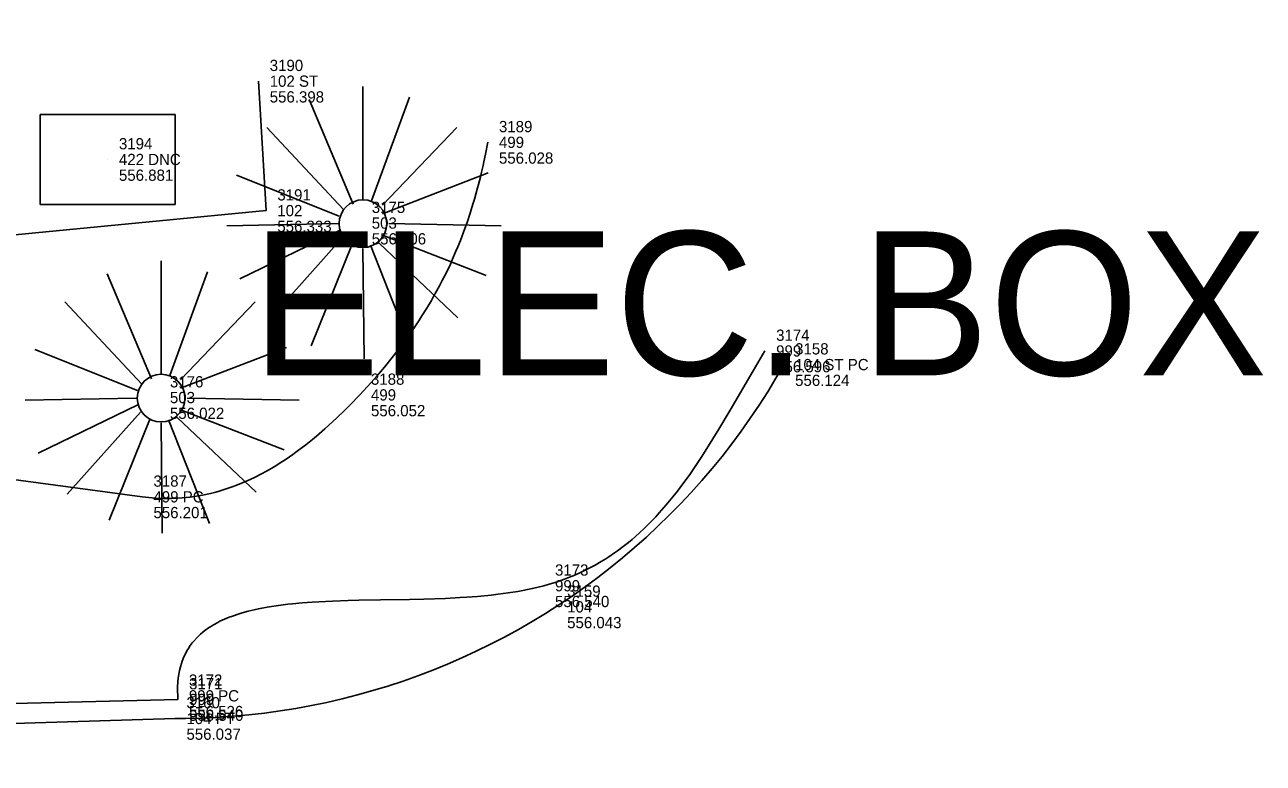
# Model space of a CAD drawing. Extents: x 5447 to 709667, y 4528 to 375505.
# Drawn here: x 708330.63 to 708358.18, y 374261.75 to 374278.17 of the extents above; entities that cross this region are included whole.
import ezdxf

# ---------------------------------------------------------------- set-up
doc = ezdxf.new("R2010")
doc.units = 0
for name, color, linetype in [('SV_BKLN_BKLN', 7, 'Continuous'), ('SV_NODES_ACTIVE_POINT', 7, 'Continuous'), ('SV_NODES_DESCRIPTION', 7, 'Continuous'), ('SV_NODES_ELEVATION', 7, 'Continuous'), ('SV_NODES_PT_NUMBER', 7, 'Continuous'), ('SV_ROAD_BCURB', 7, 'Continuous'), ('SV_ROAD_CONCRD', 7, 'Continuous'), ('SV_TREE_TREEVEG', 7, 'Continuous'), ('SV_UTAG_MISC_ELEC', 7, 'Continuous'), ('SV_UTAG_UTAG_TX', 7, 'Continuous')]:
    doc.layers.add(name, color=color, linetype=linetype)

msp = doc.modelspace()

# ---------------------------------------------------------------- linework, layer by layer
at = {"layer": 'SV_BKLN_BKLN'}
msp.add_lwpolyline([(708301.823, 374262.381), (708334.036, 374263.169), (708334.032, 374263.25), (708334.029, 374263.362), (708334.029, 374263.434), (708334.037, 374263.574), (708334.044, 374263.641), (708334.05, 374263.685), (708334.064, 374263.771), (708334.072, 374263.812), (708334.092, 374263.893), (708334.115, 374263.971), (708334.132, 374264.022), (708334.171, 374264.119), (708334.195, 374264.172), (708334.213, 374264.206), (708334.25, 374264.272), (708334.27, 374264.305), (708334.311, 374264.367), (708334.356, 374264.427), (708334.388, 374264.466), (708334.455, 374264.54), (708334.536, 374264.618), (708334.594, 374264.667), (708334.634, 374264.699), (708334.718, 374264.759), (708334.784, 374264.802), (708334.83, 374264.829), (708334.924, 374264.881), (708334.972, 374264.906), (708335.073, 374264.953), (708335.177, 374264.996), (708335.249, 374265.023), (708335.398, 374265.074), (708335.463, 374265.093), (708335.596, 374265.13), (708335.734, 374265.163), (708335.828, 374265.184), (708336.021, 374265.22), (708336.17, 374265.244), (708336.272, 374265.259), (708336.479, 374265.285), (708336.585, 374265.296), (708336.801, 374265.316), (708337.022, 374265.332), (708337.171, 374265.341), (708337.475, 374265.356), (708337.825, 374265.367), (708338.061, 374265.373), (708338.54, 374265.382), (708339.186, 374265.393), (708339.509, 374265.401), (708339.991, 374265.417), (708340.309, 374265.434), (708340.466, 374265.443), (708340.7, 374265.461), (708341.008, 374265.49), (708341.159, 374265.508), (708341.382, 374265.538), (708341.601, 374265.572), (708341.708, 374265.592), (708341.919, 374265.635), (708342.023, 374265.659), (708342.175, 374265.697), (708342.27, 374265.723), (708342.454, 374265.78), (708342.634, 374265.843), (708342.75, 374265.888), (708342.827, 374265.919), (708342.977, 374265.985), (708343.14, 374266.064), (708343.247, 374266.119), (708343.317, 374266.157), (708343.454, 374266.236), (708343.555, 374266.298), (708343.621, 374266.341), (708343.75, 374266.428), (708343.814, 374266.473), (708343.938, 374266.566), (708344.06, 374266.662), (708344.139, 374266.728), (708344.294, 374266.864), (708344.421, 374266.983), (708344.504, 374267.064), (708344.666, 374267.231), (708344.745, 374267.317), (708344.899, 374267.493), (708345.049, 374267.675), (708345.146, 374267.799), (708345.21, 374267.883), (708345.336, 374268.054), (708345.406, 374268.151), (708345.543, 374268.349), (708345.677, 374268.551), (708345.765, 374268.687), (708345.939, 374268.964), (708346.068, 374269.175), (708346.322, 374269.604), (708346.832, 374270.478), (708347.093, 374270.917)], dxfattribs=at)
at = {"layer": 'SV_NODES_ACTIVE_POINT'}
for p, q in [((708335.829, 374276.915), (708335.829, 374276.915)), ((708340.928, 374275.555), (708340.928, 374275.555)), ((708335.998, 374274.037), (708335.998, 374274.037)), ((708347.093, 374270.917), (708347.093, 374270.917)), ((708347.516, 374270.614), (708347.516, 374270.614)), ((708338.081, 374269.94), (708338.081, 374269.94)), ((708333.243, 374267.674), (708333.243, 374267.674)), ((708342.175, 374265.697), (708342.175, 374265.697)), ((708342.445, 374265.228), (708342.445, 374265.228)), ((708334.032, 374263.25), (708334.032, 374263.25)), ((708334.036, 374263.169), (708334.036, 374263.169)), ((708333.977, 374262.747), (708333.977, 374262.747))]:
    msp.add_line(p, q, dxfattribs=at)
at = {"layer": 'SV_ROAD_BCURB'}
msp.add_lwpolyline([(708347.516, 374270.614), (708347.34, 374270.31), (708347.156, 374270.009), (708346.966, 374269.713), (708346.769, 374269.422), (708346.566, 374269.134), (708346.356, 374268.852), (708346.14, 374268.574), (708345.917, 374268.302), (708345.689, 374268.034), (708345.454, 374267.772), (708345.214, 374267.515), (708344.967, 374267.264), (708344.715, 374267.018), (708344.458, 374266.779), (708344.195, 374266.545), (708343.927, 374266.317), (708343.654, 374266.095), (708343.375, 374265.88), (708343.092, 374265.671), (708342.805, 374265.468), (708342.512, 374265.272), (708342.216, 374265.083), (708341.915, 374264.9), (708341.61, 374264.725), (708341.301, 374264.556), (708340.989, 374264.395), (708340.673, 374264.24), (708340.353, 374264.093), (708340.03, 374263.953), (708339.704, 374263.821), (708339.375, 374263.696), (708339.044, 374263.578), (708338.709, 374263.468), (708338.373, 374263.366), (708338.034, 374263.271), (708337.693, 374263.184), (708337.35, 374263.105), (708337.005, 374263.034), (708336.659, 374262.97), (708336.312, 374262.914), (708335.963, 374262.867), (708335.614, 374262.827), (708335.263, 374262.795), (708334.912, 374262.771), (708334.561, 374262.756), (708334.209, 374262.748), (708333.977, 374262.747), (708301.876, 374261.752)], dxfattribs=at)
at = {"layer": 'SV_ROAD_CONCRD'}
msp.add_lwpolyline([(708335.829, 374276.915), (708335.998, 374274.037), (708329.18, 374273.382), (708328.681, 374278.168)], dxfattribs=at)
at = {"layer": 'SV_TREE_TREEVEG'}
for p, q in [((708338.153, 374274.277), (708338.153, 374276.799)), ((708336.953, 374276.51), (708337.938, 374274.179)), ((708339.186, 374276.557), (708338.345, 374274.251)), ((708336.014, 374275.886), (708337.721, 374274.059)), ((708338.587, 374274.157), (708340.244, 374275.886)), ((708337.627, 374273.914), (708335.343, 374274.828)), ((708338.587, 374273.965), (708340.94, 374274.875)), ((708337.601, 374273.747), (708335.126, 374273.7)), ((708337.649, 374273.603), (708335.416, 374272.522)), ((708338.729, 374273.747), (708341.227, 374273.7)), ((708337.696, 374273.436), (708336.064, 374271.609)), ((708337.913, 374273.291), (708337, 374271.032)), ((708338.512, 374273.316), (708340.266, 374271.656)), ((708338.609, 374273.483), (708340.893, 374272.595)), ((708338.153, 374273.196), (708338.178, 374270.743)), ((708338.319, 374273.266), (708339.233, 374270.96)), ((708333.663, 374270.398), (708333.663, 374272.92)), ((708332.463, 374272.631), (708333.448, 374270.3)), ((708334.696, 374272.678), (708333.855, 374270.372)), ((708331.524, 374272.007), (708333.231, 374270.18)), ((708334.097, 374270.278), (708335.754, 374272.007)), ((708333.137, 374270.035), (708330.853, 374270.949)), ((708334.097, 374270.086), (708336.45, 374270.996)), ((708333.111, 374269.868), (708330.636, 374269.821)), ((708333.159, 374269.724), (708330.926, 374268.643)), ((708334.239, 374269.868), (708336.737, 374269.821)), ((708333.206, 374269.557), (708331.574, 374267.73)), ((708334.022, 374269.437), (708335.776, 374267.777)), ((708334.119, 374269.604), (708336.403, 374268.716)), ((708333.423, 374269.412), (708332.51, 374267.153)), ((708333.663, 374269.317), (708333.688, 374266.864)), ((708333.829, 374269.387), (708334.743, 374267.081))]:
    msp.add_line(p, q, dxfattribs=at)
msp.add_lwpolyline([(708320.673, 374269.366), (708333.243, 374267.674), (708333.317, 374267.664), (708333.464, 374267.65), (708333.609, 374267.64), (708333.705, 374267.637), (708333.895, 374267.637), (708334.036, 374267.643), (708334.129, 374267.649), (708334.313, 374267.669), (708334.405, 374267.681), (708334.585, 374267.712), (708334.763, 374267.751), (708334.88, 374267.781), (708334.958, 374267.803), (708335.112, 374267.85), (708335.24, 374267.894), (708335.324, 374267.925), (708335.491, 374267.993), (708335.574, 374268.029), (708335.738, 374268.105), (708335.899, 374268.187), (708336.004, 374268.245), (708336.075, 374268.284), (708336.213, 374268.366), (708336.29, 374268.414), (708336.443, 374268.513), (708336.592, 374268.616), (708336.691, 374268.687), (708336.885, 374268.833), (708337.027, 374268.947), (708337.121, 374269.025), (708337.305, 374269.183), (708337.396, 374269.264), (708337.574, 374269.429), (708337.747, 374269.597), (708337.86, 374269.71), (708338.081, 374269.94), (708338.25, 374270.121), (708338.332, 374270.212), (708338.454, 374270.35), (708338.631, 374270.558), (708338.803, 374270.768), (708338.886, 374270.874), (708339.049, 374271.089), (708339.128, 374271.197), (708339.244, 374271.361), (708339.394, 374271.583), (708339.466, 374271.695), (708339.572, 374271.866), (708339.675, 374272.039), (708339.725, 374272.126), (708339.855, 374272.362), (708339.918, 374272.482), (708340.009, 374272.664), (708340.097, 374272.849), (708340.139, 374272.943), (708340.222, 374273.133), (708340.262, 374273.229), (708340.321, 374273.374), (708340.421, 374273.638), (708340.468, 374273.773), (708340.537, 374273.978), (708340.57, 374274.081), (708340.612, 374274.221), (708340.633, 374274.292), (708340.664, 374274.399), (708340.703, 374274.542), (708340.722, 374274.615), (708340.764, 374274.78), (708340.791, 374274.892), (708340.825, 374275.042), (708340.842, 374275.118), (708340.878, 374275.291), (708340.928, 374275.555)], dxfattribs=at)
for centre in [(708338.153, 374273.747), (708333.663, 374269.868)]:
    msp.add_circle(centre, 0.53, dxfattribs=at)
at = {"layer": 'SV_UTAG_MISC_ELEC'}
for p, q in [((708333.974, 374276.176), (708330.976, 374276.176)), ((708330.976, 374276.176), (708330.976, 374274.172)), ((708333.974, 374274.172), (708333.974, 374276.176)), ((708332.475, 374275.174), (708332.475, 374275.174)), ((708330.976, 374274.172), (708333.974, 374274.172))]:
    msp.add_line(p, q, dxfattribs=at)

# ---------------------------------------------------------------- texts
at = {"layer": 'SV_NODES_DESCRIPTION'}
for s, p in [('102 ST', (708336.079, 374276.79)), ('499', (708341.178, 374275.43)), ('422 DNC', (708332.725, 374275.049)), ('102', (708336.248, 374273.912)), ('503', (708338.349, 374273.635)), ('999', (708347.343, 374270.792)), ('104 ST PC', (708347.766, 374270.489)), ('503', (708333.859, 374269.756)), ('499', (708338.331, 374269.815)), ('499 PC', (708333.493, 374267.549)), ('999', (708342.425, 374265.572)), ('104', (708342.695, 374265.103)), ('999 PC', (708334.282, 374263.125)), ('999', (708334.286, 374263.044)), ('104 PT', (708334.227, 374262.622))]:
    msp.add_text(s, height=0.25, dxfattribs=at).set_placement(p)
at = {"layer": 'SV_NODES_ELEVATION'}
for s, p in [('556.398', (708336.079, 374276.44)), ('556.028', (708341.178, 374275.08)), ('556.881', (708332.725, 374274.699)), ('556.333', (708336.248, 374273.562)), ('556.206', (708338.349, 374273.285)), ('556.596', (708347.343, 374270.442)), ('556.124', (708347.766, 374270.139)), ('556.052', (708338.331, 374269.465)), ('556.022', (708333.859, 374269.406)), ('556.201', (708333.493, 374267.199)), ('556.540', (708342.425, 374265.222)), ('556.043', (708342.695, 374264.753)), ('556.526', (708334.282, 374262.775)), ('556.540', (708334.286, 374262.694)), ('556.037', (708334.227, 374262.272))]:
    msp.add_text(s, height=0.25, dxfattribs=at).set_placement(p)
at = {"layer": 'SV_NODES_PT_NUMBER'}
for s, p in [('3190', (708336.079, 374277.14)), ('3189', (708341.178, 374275.78)), ('3194', (708332.725, 374275.399)), ('3191', (708336.248, 374274.262)), ('3175', (708338.349, 374273.985)), ('3174', (708347.343, 374271.142)), ('3158', (708347.766, 374270.839)), ('3176', (708333.859, 374270.106)), ('3188', (708338.331, 374270.165)), ('3187', (708333.493, 374267.899)), ('3173', (708342.425, 374265.922)), ('3159', (708342.695, 374265.453)), ('3172', (708334.282, 374263.475)), ('3171', (708334.286, 374263.394)), ('3160', (708334.227, 374262.972))]:
    msp.add_text(s, height=0.25, dxfattribs=at).set_placement(p)
at = {"layer": 'SV_UTAG_UTAG_TX'}
msp.add_text('ELEC. BOX', height=3.2, dxfattribs=at).set_placement((708335.675, 374270.374))

doc.saveas('drawing.dxf')
